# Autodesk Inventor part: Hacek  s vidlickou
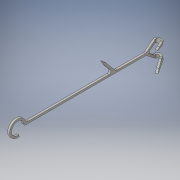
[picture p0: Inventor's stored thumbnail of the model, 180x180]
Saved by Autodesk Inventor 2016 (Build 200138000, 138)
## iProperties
Created: 2015-07
Part Number: Hacek  s vidlickou
Material: Všeobecné
Document SubType Name: Plech
Designer: brecka
Density: 1 g/cm^3
Sheet Metal Rule: Výchozí
Sheet Metal Width: 37 mm
Sheet Metal Length: 257 mm
Sheet Metal Area: 9416 mm^2
Appearance: Výchozí
Flat Pattern Width: 3.65892 cm
Flat Pattern Length: 25.7354 cm
Flat Pattern Area: 94.1636 cm^2
Author: brecka
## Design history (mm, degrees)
sketch "Náčrt1"
  geometry: L1 (-12.304, 210.425)-(-9.351, 210.954); L2 (-12.304, 210.425)-(-9.351, 210.954); L3 (0, 212.63)-(-12.304, 210.425); L4 (1.5, 59.25)-(1.5, 15); L5 (19.102, 76.351)-(3.286, 63.08); L6 (0, 62.281)-(23.5, 82); L7 (6.428, 69.633)-(17.174, 78.65); L8 (23.5, 82)-(23.5, 82); L9 (1.5, 195.719)-(1.5, 71.931); L10 (-1.5, 200.221)-(-1.5, 15); L11 (0, 1.63)-(0, 201.63); L12 (-1.5, 15)-(-10.859, 2.803); L13 (-10.859, 2.803)-(-30.043, -22.198); L14 (-30.043, -22.198)-(-27.663, -24.024); L15 (-27.663, -24.024)-(0, 12.027); L16 (0, 12.027)-(27.663, -24.024); L17 (27.663, -24.024)-(30.043, -22.198); L18 (30.043, -22.198)-(1.5, 15); L19 (10.958, -2.254)-(13.338, -0.427); L20 (-10.958, -2.254)-(-13.338, -0.427); L21 (23.5, 82)-(17.174, 78.65); L22 (23.5, 82)-(19.102, 76.351); L23 (13.338, -0.427)-(8.444, 1.022); L24 (-13.338, -0.427)-(-8.444, 1.022); L25 (-13.338, -0.427)-(-8.444, 1.022); L26 (0, 12.027)-(-8.444, 1.022); L27 (-8.444, 1.022)-(-13.338, -0.427); L28 (-13.338, -0.427)-(-1.5, 15); A1 r 6 centre (7.5, 195.719) between (5.068, 201.204) and (1.5, 195.719); A2 r 3 centre (1.5, 200.221) between (1.14, 203.199) and (-1.5, 200.221); A3 r 9.5 centre (0, 212.63) between (1.14, 203.199) and (-9.351, 210.954); A4 r 11 centre (0, 212.63) between (0, 201.63) and (-10.508, 209.376); A5 r 12.5 centre (0, 212.63) between (5.068, 201.204) and (-12.304, 210.425); A6 r 5 centre (6.5, 59.25) between (3.286, 63.08) and (1.5, 59.25); A7 r 3 centre (4.5, 71.931) between (1.5, 71.931) and (6.428, 69.633); 5 further points
  constraints: 56 end point, 16 point on circle, 15 point on line, 8 tangent, 7 centre point, 7 collinear, 4 perpendicular, 2 parallel, 1 vertical, 5 other
  dimensions: "d3" = 3 diameter of L5 L6; "d4" = 0 distance from line of L6.end L8; "d5" = 3 diameter of L10 L11; "d9" = 3 radius of A7; "d10" = 5 radius of A6; "d11" = 200 distance of L11.start L11.end; "d12" = 11 radius of A4; "d13" = 1.5 radial gap between concentric circles of A4 A3; "d14" = 11 distance of point (-1.5, 203.25) L1.end; "d15" = 6 radius of A1; "d16" = 3 radius of A2; "d17" = 0 distance from line of L3.start L11; "d18" = 1.5 radial gap between concentric circles of A5 A4 (= d13); "d20" = 0 distance of L11.end A4.start; "d21" = 82 vertical distance of L6.end point (0, 0); "d22" = 0 distance from line of point (0, 0) L11; "d23" = 50 deg angle of L11 L6; "d24" = 3 distance between parallel lines of L15 L13; "d25" = 75 deg angle of L15 L16; "d26" = 15 vertical distance of L4.end point (0, 0); "d27" = 3 distance of L16.end L17.end (derived); "d28" = 18 distance from line of L15.end L19; "d29" = 18 distance from line of L15.end L20 (= d28); "d30" = 22 distance from line of L6.end L9; "d31" = 1.5 distance of L8.start point (22.536, 83.149); "d32" = 7 distance of L7.end point (22.536, 83.149); "d33" = 1.5 distance of L8.end point (24.464, 80.851) (= d31); "d34" = 7 distance of L5.start point (24.464, 80.851) (= d32); "d72" = 54 deg angle of L19 L23; "d73" = 54 deg angle of L24 L20 (= d72)
node "Plocha1"
node "Obruba3"
sketch "Náčrt5"
  geometry: L1 (-22.608, 5.104)-(-22.608, 0) reference; L2 (0, 0)-(-22.608, 0) reference; L3 (0, 0)-(0, 5.104) reference; L4 (0, 5.104)-(-22.608, 5.104) reference; L5 (0, 2.552)-(-7, 1.052); L6 (-7, 1.052)-(-20.608, 0); L7 (-22.608, 0)-(0, 0) reference; L8 (0, 2.552)-(-7, 4.052); L9 (-7, 4.052)-(-20.608, 5.104); L10 (-22.608, 5.104)-(-22.608, 0) reference; L11 (-22.608, 2.552)-(0, 2.552); L12 (0, 0)-(0, 5.104) reference; L13 (0, 5.104)-(-22.608, 5.104) reference; L14 (-20.608, 5.104)-(0, 5.104); L15 (0, 5.104)-(0, 0); L16 (0, 0)-(-20.608, 0); 1 further point
  constraints: 16 end point, 3 collinear, 2 midpoint, 2 point on line, 1 equal length, 1 perpendicular, 1 other
  dimensions: "d86" = 1.5 vertical distance of L5.end L5.start; "d87" = 7 horizontal distance of L5.start L5.end; "d88" = 2 distance from line of L6.end L1
extrude "Vysunutí2" cut sketch "Náčrt5" distance "d89" = 3; taper "d90" = 0 deg
mirror "Zrcadlit1"
fillet "Zaoblení1" dims "d91" = 3
node "Těleso2"
feature "Deska3" dims "Tloušťka" = 3 (derived)
sketch "Náčrt4"
  geometry: L1 (-4.829, 1.652)-(0, 0); L2 (0, 0)-(7.317, 21.391); L3 (7.317, 21.391)-(2.487, 23.043); L4 (2.487, 23.043)-(-4.829, 1.652)
  constraints: 8 end point
feature "Deska4" dims "d60" = 3 (= ŠířkaVýštipu), "d61" = 1.5 (= HloubkaVýštipu), "d62" = 6 (= MinimálníZbytek), "d63" = 3 (= PoloměrOhybu), "d64" = 45, "d65" = 150 deg, "d66" = 3 (= PoloměrOhybu), "d67" = 12 (= VelikostRohovéhoVýštipu), "d68" = 3 (= VelikostMezery), "d69" = 3 (= VelikostJacobihoPoloměru), "Tloušťka" = 3 (derived), "MezeraVystřižení" = 0.01
feature "Ohyb3" dims "d60" = 3 (= ŠířkaVýštipu), "d61" = 1.5 (= HloubkaVýštipu), "d62" = 6 (= MinimálníZbytek), "d63" = 3 (= PoloměrOhybu), "d64" = 45, "d65" = 150 deg, "d66" = 3 (= PoloměrOhybu), "Tloušťka" = 3 (derived), "MezeraVystřižení" = 0.01
feature "Roh3" dims "d64" = 45, "d65" = 150 deg, "d67" = 12 (= VelikostRohovéhoVýštipu), "d68" = 3 (= VelikostMezery), "d69" = 3 (= VelikostJacobihoPoloměru)
node "Promítnutá smyčka1"
feature "Definice1"
other parameters: "KSoučinitel" = 4.4, "PoloměrOhybu" = 3 (= Tloušťka), "ŠířkaVýštipu" = 3 (= Tloušťka), "HloubkaVýštipu" = 1.5 (= 0.5 x Tloušťka), "VelikostRohovéhoVýštipu" = 12 (= 4 x Tloušťka), "MinimálníZbytek" = 6 (= 2 x Tloušťka), "PřechodovýPoloměr" = 3 (= PoloměrOhybu), "VelikostJacobihoPoloměru" = 3 (= Tloušťka), "VelikostMezery" = 3 (= Tloušťka), "d59" = 3 (= PoloměrOhybu), "HloubkaVýštipu" = 1.5, "MinimálníZbytek" = 6, "PoloměrOhybu" = 3, "PřechodovýPoloměr" = 3, "Tloušťka" = 3, "VelikostJacobihoPoloměru" = 3, "VelikostMezery" = 3, "VelikostRohovéhoVýštipu" = 12, "ŠířkaVýštipu" = 3
